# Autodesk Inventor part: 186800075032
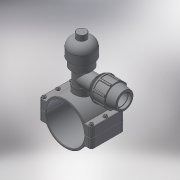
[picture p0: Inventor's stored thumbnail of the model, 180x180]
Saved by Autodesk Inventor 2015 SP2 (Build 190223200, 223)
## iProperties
Created: 2017-05
Part Number: 186800075032
Material: Generic
Description: PLASSON MECHANICAL TAPPING VALVE 75-32
Document SubType Name: Modeling
Designer: KIM
Density: 1 g/cm^3
Appearance: Default
Author: KIM
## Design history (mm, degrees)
derived "18680.ipt"
feature "Solid1::18680.ipt"
feature "Solid2::18680.ipt"
tag "TaggingFeature1"
body "Solid1"
other parameters: "d0" = 93.75, "d1" = 122, "d2" = 37.5, "d3" = 75, "d4" = 98, "d5" = 0, "d6" = 6.1, "d7" = 122, "d8" = 0.1, "d10" = 0, "d11" = 0.75, "d14" = 50.6376, "d20" = 0.75, "d23" = 0.75, "d37" = 8, "d38" = 45.5, "d39" = 0, "d40" = 3, "d41" = 5, "d42" = 0, "d43" = 6, "d44" = 3, "d45" = 0, "d46" = 0.75, "d51" = 72, "d52" = 38.952, "d53" = 25, "d54" = 0, "d55" = 32, "d57" = 0, "d58" = 81, "d60" = 0, "d63" = 8, "d66" = 82, "d67" = 32, "d68" = 11.25, "d69" = 27, "d70" = 64, "d71" = 48, "d72" = 1.92857, "d73" = 51.2, "d74" = 120 deg, "d75" = 48, "d76" = 10 deg, "d77" = 57.6, "d78" = 40.5, "d79" = 67, "d80" = 25.6, "d81" = 135, "d82" = 6.7, "d87" = 19.28571, "d90" = 59.52, "d91" = 35 deg, "d92" = 17.5 deg, "d94" = 0, "d96" = 360 deg, "d98" = 0.64, "d99" = 73.7, "d100" = 38.4, "d101" = 135 deg, "d102" = 1.28, "d105" = 3.2, "d106" = 0, "d107" = 0.1, "d109" = 50.6376, "d112" = 34.85714, "d113" = 4.5, "d116" = 0, "d121" = 46.7424, "d122" = 77.904, "d123" = 66.2184, "d124" = 45 deg, "d125" = 219.6, "d126" = 244, "d127" = 146.4, "d128" = 1, "d_" = 75, "B_" = 32, "G_" = 38.952, "A_" = 72, "L_" = 122, "L_1" = 98, "l_2" = 25, "d_1" = 32, "E_" = 64, "l_" = 67, "H_" = 135, "H_2" = 244
